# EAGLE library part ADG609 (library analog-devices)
3 V/5 V, 4 Channel High Performance Analog Multiplexers Source: ADG608_609.pdf
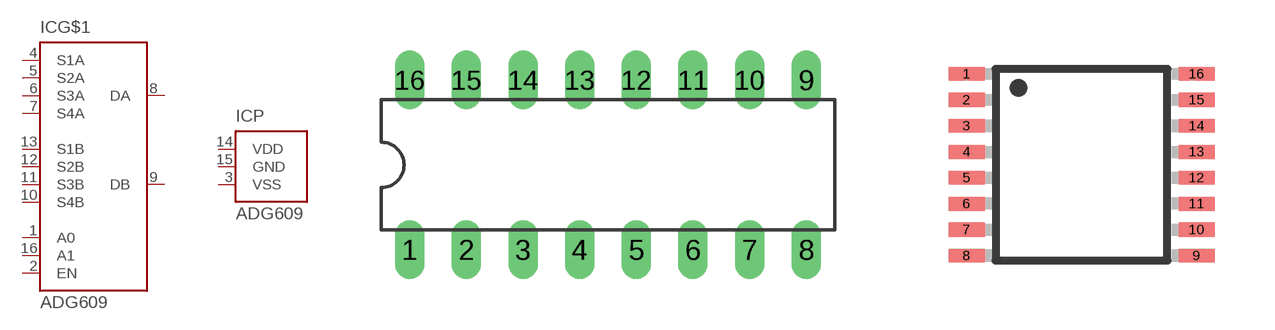
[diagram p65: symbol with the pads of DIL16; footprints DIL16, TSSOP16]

Designator prefix IC; gates G$1=ADG1409 P=PWR-VSS_GND_VDD

## ADG609N (MF: ALTERA CORPORATION; MPN: ADG609BN; OC_FARNELL: 1438945; OC_NEWARK: 66F3790)  [DIL16]
1  G$1:A0  in
2  G$1:EN  in
3  P:VSS  pwr
4  G$1:S1A
5  G$1:S2A
6  G$1:S3A
7  G$1:S4A
8  G$1:DA
9  G$1:DB
10  G$1:S4B
11  G$1:S3B
12  G$1:S2B
13  G$1:S1B
14  P:VDD  pwr
15  P:GND  pwr
16  G$1:A1  in

## ADG609RU (MPN: ADG609BRUZ; OC_FARNELL: 1438945; OC_NEWARK: 19M8664)  [TSSOP16]
Pads as for DIL16

## ADG609R (MPN: ADG609BRZ; OC_FARNELL: 1438945; OC_NEWARK: 15P0386)  [SOIC16N]
Pads as for DIL16

## Footprint DIL16 (pad centres in mm)
Dual In Line Package
drill 0.813 long: 1 -8.89,-3.81; 2 -6.35,-3.81; 3 -3.81,-3.81; 4 -1.27,-3.81; 5 1.27,-3.81; 6 3.81,-3.81; 7 6.35,-3.81; 8 8.89,-3.81; 9 8.89,3.81; 10 6.35,3.81; 11 3.81,3.81; 12 1.27,3.81; 13 -1.27,3.81; 14 -3.81,3.81; 15 -6.35,3.81; 16 -8.89,3.81

## Footprint TSSOP16 (pad centres in mm)
16-Lead Thin Shrink Small Outline Package [TSSOP] (RU-16) Source: 8x ADG1408_1409.pdf
smd 0.9 x 0.35: 1 -2.875,2.275; 2 -2.875,1.625; 3 -2.875,0.975; 4 -2.875,0.325; 5 -2.875,-0.325; 6 -2.875,-0.975; 7 -2.875,-1.625; 8 -2.875,-2.275; 9 2.875,-2.275; 10 2.875,-1.625; 11 2.875,-0.975; 12 2.875,-0.325; 13 2.875,0.325; 14 2.875,0.975; 15 2.875,1.625; 16 2.875,2.275

## Footprint SOIC16N (pad centres in mm)
SMALL OUTLINE INTEGRATED CIRCUIT
smd 0.6 x 2.2: 1 -4.445,-2.6; 2 -3.175,-2.6; 3 -1.905,-2.6; 4 -0.635,-2.6; 5 0.635,-2.6; 6 1.905,-2.6; 7 3.175,-2.6; 8 4.445,-2.6; 9 4.445,2.6; 10 3.175,2.6; 11 1.905,2.6; 12 0.635,2.6; 13 -0.635,2.6; 14 -1.905,2.6; 15 -3.175,2.6; 16 -4.445,2.6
